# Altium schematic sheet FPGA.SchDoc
size A
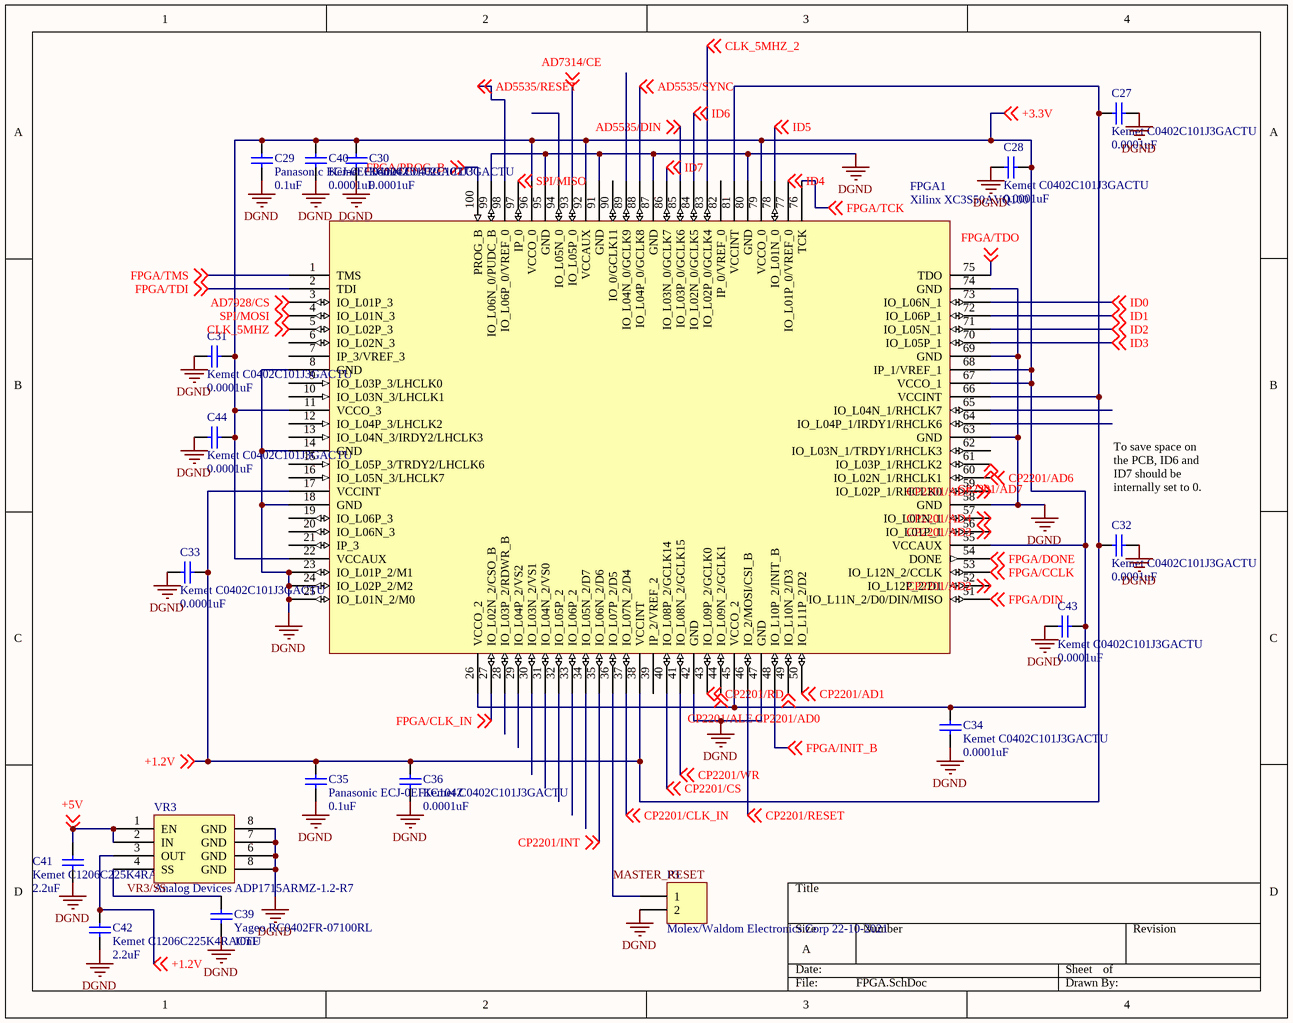
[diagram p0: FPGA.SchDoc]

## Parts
C27  Kemet C0402C101J3GACTU  value 0.0001uF  [0402]
C28  Kemet C0402C101J3GACTU  value 0.0001uF  [0402]
C29  Panasonic ECJ-0EF1C104Z  value 0.1uF  [0402]
C30  Kemet C0402C101J3GACTU  value 0.0001uF  [0402]
C31  Kemet C0402C101J3GACTU  value 0.0001uF  [0402]
C32  Kemet C0402C101J3GACTU  value 0.0001uF  [0402]
C33  Kemet C0402C101J3GACTU  value 0.0001uF  [0402]
C34  Kemet C0402C101J3GACTU  value 0.0001uF  [0402]
C35  Panasonic ECJ-0EF1C104Z  value 0.1uF  [0402]
C36  Kemet C0402C101J3GACTU  value 0.0001uF  [0402]
C39  Yageo RC0402FR-07100RL  value 10nF  [C1206]
C40  Kemet C0402C101J3GACTU  value 0.0001uF  [0402]
C41  Kemet C1206C225K4RACTU  value 2.2uF  [C1206]
C42  Kemet C1206C225K4RACTU  value 2.2uF  [C1206]
C43  Kemet C0402C101J3GACTU  value 0.0001uF  [0402]
C44  Kemet C0402C101J3GACTU  value 0.0001uF  [0402]
FPGA1  Xilinx XC3S50AVQ100  [VQ100_L]
P3  Molex/Waldom Electronics Corp 22-10-2021  [HDR1X2]
VR3  Analog Devices ADP1715ARMZ-1.2-R7  [RM-8]

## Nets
DGND: C27.1 C28.1 C29.1 C30.1 C31.1 C32.1 C33.1 C34.1 C35.1 C36.1 C39.1 C40.1 C41.1 C42.1 C43.2 C44.1 FPGA1.8(GND) FPGA1.14(GND) FPGA1.18(GND) FPGA1.23(IO_L01P_2/M1) FPGA1.24(IO_L02P_2/M2) FPGA1.25(IO_L01N_2/M0) FPGA1.42(GND) FPGA1.47(GND) FPGA1.58(GND) FPGA1.63(GND) FPGA1.69(GND) FPGA1.74(GND) FPGA1.80(GND) FPGA1.87(GND) FPGA1.91(GND) FPGA1.95(GND) FPGA1.99(IO_L06N_0/PUDC_B) P3.2 VR3.6(GND) VR3.7(GND) VR3.8(GND)
+1.2V: C27.2 C32.2 C33.2 C35.2 C36.2 C42.2 FPGA1.17(VCCINT) FPGA1.38(VCCINT) FPGA1.66(VCCINT) FPGA1.81(VCCINT) VR3.3(OUT) ; off-sheet +1.2V
+3.3V: C28.2 C29.2 C30.2 C31.2 C34.2 C40.2 C43.1 C44.2 FPGA1.11(VCCO_3) FPGA1.22(VCCAUX) FPGA1.26(VCCO_2) FPGA1.45(VCCO_2) FPGA1.55(VCCAUX) FPGA1.67(VCCO_1) FPGA1.68(IP_1/VREF_1) FPGA1.79(VCCO_0) FPGA1.92(VCCAUX) FPGA1.96(VCCO_0) ; off-sheet +3.3V
+5V: C41.2 VR3.1(EN) VR3.2(IN) ; off-sheet +5V
AD5535/DIN: FPGA1.85(IO_L03P_0/GCLK6) ; off-sheet AD5535/DIN
AD5535/RESET: FPGA1.98(IO_L06P_0/VREF_0) ; off-sheet AD5535/RESET
AD5535/SYNC: FPGA1.88(IO_L04P_0/GCLK8) ; off-sheet AD5535/SYNC
AD7314/CE: FPGA1.93(IO_L05P_0) ; off-sheet AD7314/CE
AD7928/CS: FPGA1.3(IO_L01P_3) ; off-sheet AD7928/CS
CLK_5MHZ: FPGA1.5(IO_L02P_3) ; off-sheet CLK_5MHZ
CLK_5MHZ_2: FPGA1.83(IO_L02P_0/GCLK4) ; off-sheet CLK_5MHZ_2
CP2201/AD0: FPGA1.49(IO_L10N_2/D3) ; off-sheet CP2201/AD0
CP2201/AD1: FPGA1.50(IO_L11P_2/D2) ; off-sheet CP2201/AD1
CP2201/AD2: FPGA1.52(IO_L12P_2/D1) ; off-sheet CP2201/AD2
CP2201/AD3: FPGA1.56(IO_L01P_1) ; off-sheet CP2201/AD3
CP2201/AD4: FPGA1.57(IO_L01N_1) ; off-sheet CP2201/AD4
CP2201/AD5: FPGA1.59(IO_L02P_1/RHCLK0) ; off-sheet CP2201/AD5
CP2201/AD6: FPGA1.60(IO_L02N_1/RHCLK1) ; off-sheet CP2201/AD6
CP2201/AD7: FPGA1.61(IO_L03P_1/RHCLK2) ; off-sheet CP2201/AD7
CP2201/ALE: FPGA1.44(IO_L09N_2/GCLK1) ; off-sheet CP2201/ALE
CP2201/CLK_IN: FPGA1.37(IO_L07N_2/D4) ; off-sheet CP2201/CLK_IN
CP2201/CS: FPGA1.40(IO_L08P_2/GCLK14) ; off-sheet CP2201/CS
CP2201/INT: FPGA1.35(IO_L06N_2/D6) ; off-sheet CP2201/INT
CP2201/RD: FPGA1.43(IO_L09P_2/GCLK0) ; off-sheet CP2201/RD
CP2201/RESET: FPGA1.46(IO_2/MOSI/CSI_B) ; off-sheet CP2201/RESET
CP2201/WR: FPGA1.41(IO_L08N_2/GCLK15) ; off-sheet CP2201/WR
FPGA/CCLK: FPGA1.53(IO_L12N_2/CCLK) ; off-sheet FPGA/CCLK
FPGA/CLK_IN: FPGA1.27(IO_L02N_2/CSO_B) ; off-sheet FPGA/CLK_IN
FPGA/DIN: FPGA1.51(IO_L11N_2/D0/DIN/MISO) ; off-sheet FPGA/DIN
FPGA/DONE: FPGA1.54(DONE) ; off-sheet FPGA/DONE
FPGA/INIT_B: FPGA1.48(IO_L10P_2/INIT_B) ; off-sheet FPGA/INIT_B
FPGA/PROG_B: FPGA1.100(PROG_B) ; off-sheet FPGA/PROG_B
FPGA/TCK: FPGA1.76(TCK) ; off-sheet FPGA/TCK
FPGA/TDI: FPGA1.2(TDI) ; off-sheet FPGA/TDI
FPGA/TDO: FPGA1.75(TDO) ; off-sheet FPGA/TDO
FPGA/TMS: FPGA1.1(TMS) ; off-sheet FPGA/TMS
ID0: FPGA1.73(IO_L06N_1) ; off-sheet ID0
ID1: FPGA1.72(IO_L06P_1) ; off-sheet ID1
ID2: FPGA1.71(IO_L05N_1) ; off-sheet ID2
ID3: FPGA1.70(IO_L05P_1) ; off-sheet ID3
ID4: FPGA1.77(IO_L01P_0/VREF_0) ; off-sheet ID4
ID5: FPGA1.78(IO_L01N_0) ; off-sheet ID5
ID6: FPGA1.84(IO_L02N_0/GCLK5) ; off-sheet ID6
ID7: FPGA1.86(IO_L03N_0/GCLK7) ; off-sheet ID7
MASTER_RESET: FPGA1.36(IO_L07P_2/D5) P3.1
SPI/MISO: FPGA1.97(IP_0) ; off-sheet SPI/MISO
SPI/MOSI: FPGA1.4(IO_L01N_3) ; off-sheet SPI/MOSI
VR3/SS: C39.2 VR3.4(SS)

Not connected (* = marked no-connect by the designer): FPGA1 6(IO_L02N_3) 7(IP_3/VREF_3) 9(IO_L03P_3/LHCLK0) 10(IO_L03N_3/LHCLK1) 12(IO_L04P_3/LHCLK2) 13(IO_L04N_3/IRDY2/LHCLK3) 15(IO_L05P_3/TRDY2/LHCLK6) 16(IO_L05N_3/LHCLK7) 19(IO_L06P_3) 20(IO_L06N_3) 21(IP_3) 28(IO_L03P_2/RDWR_B) 29(IO_L04P_2/VS2) 30(IO_L03N_2/VS1) 31(IO_L04N_2/VS0) 32(IO_L05P_2) 33(IO_L06P_2) 34(IO_L05N_2/D7) 39(IP_2/VREF_2) 62(IO_L03N_1/TRDY1/RHCLK3) 64(IO_L04P_1/IRDY1/RHCLK6) 65(IO_L04N_1/RHCLK7) 82(IP_0/VREF_0) 89(IO_L04N_0/GCLK9) 90(IO_0/GCLK11) 94(IO_L05N_0)

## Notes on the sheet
- (near C32) To save space on the PCB, ID6 and ID7 should be internally set to 0.

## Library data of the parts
C27-C36 C39-C44 = Cap: Capacitor
FPGA1 = XC3S50AVQ100
P3 = Header 2: Header, 2-Pin
VR3 = ADP1715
